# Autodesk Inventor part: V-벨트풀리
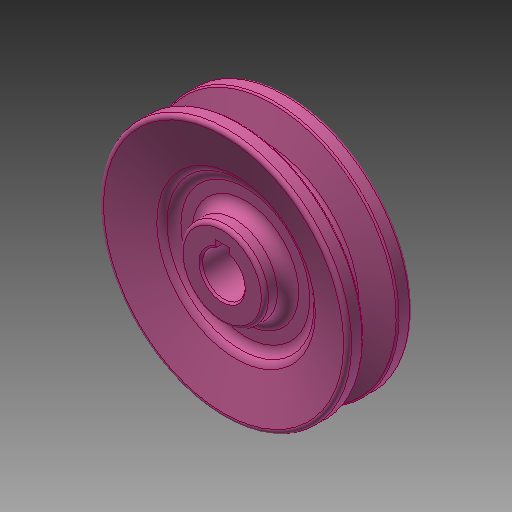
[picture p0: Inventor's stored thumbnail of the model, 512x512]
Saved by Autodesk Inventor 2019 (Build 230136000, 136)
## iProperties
Created: 2016-08
Part Number: V-벨트풀리
Material: 알루미늄 6061
Document SubType Name: Modeling
Designer: mduedu
Density: 2.71 g/cm^3
Appearance: 분홍색
Author: mduedu
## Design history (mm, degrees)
sketch "스케치1"
  geometry: L1 (0, 9.5)-(0, -9.5); L2 (0, 9.5)-(35, 9.5); L3 (35, 9.5)-(35, 4.825); L4 (35, 4.825)-(26, 2.074); L5 (26, 2.074)-(26, 0); L6 (0, 0)-(26, 0); L7 (0, -9.5)-(35, -9.5); L8 (35, -9.5)-(35, -4.825); L9 (35, -4.825)-(26, -2.074); L10 (26, -2.074)-(26, 0); L11 (32.3, 9.5)-(32.3, -9.5); 3 further points
  constraints: 22 end point, 6 point on line, 4 perpendicular, 3 symmetric about line, 1 coincident, 1 horizontal alignment, 1 midpoint, 1 parallel, 1 vertical
  dimensions: "d0" = 19 distance of L1.start L1.end; "d2" = 70 diameter of L8 L1; "d4" = 6.3 distance between parallel lines of L10 L11; "d5" = 2.7 distance between parallel lines of L11 L8; "d6" = 8 distance of point (32.3, -4) point (32.3, 4); "d7" = 34 deg angle of L9 L4
revolve "회전1" sketch "스케치1" stored, may be unused: angle "d8" = 90 deg
sketch "스케치2"
  geometry: L1 (-2, 0)-(2, 0); L2 (2, 0)-(2, 7.8); L3 (2, 7.8)-(-2, 7.8); L4 (-2, 7.8)-(-2, 0); C1 r 6 at (0, 0); 2 further points
  constraints: 8 end point, 2 coincident, 2 parallel, 1 centre point, 1 horizontal, 1 midpoint, 1 perpendicular
  dimensions: "d9" = 12 diameter of C1; "d11" = 4 distance of L2.end L3.end; "d12" = 7.8 distance of L1.end L2.end
extrude "돌출1" cut sketch "스케치2" extent not by distance; stored distance "d13" = 10; taper "d14" = 0 deg
sketch "스케치3"
  geometry: L1 (35, 4.825)-(26, 2.074) reference; L2 (26, 2.074)-(26, -2.074) reference; L3 (0, 0)-(26, 0); L4 (35, 9.5)-(35, 4.825) reference; L5 (-35, 9.5)-(35, 9.5) reference; L6 (35, 9.5)-(21, 5.22); L7 (21, 5.22)-(21, 3); L8 (21, 3)-(12, 3); L9 (12, 3)-(12, 9.5); L10 (0, 9.5)-(0, -9.5); L11 (5.657, -9.5)-(-6, -9.5) reference; L12 (12, 9.5)-(35, 9.5)
  constraints: 14 end point, 3 midpoint, 2 parallel, 2 perpendicular, 2 point on line, 1 collinear, 1 horizontal
  dimensions: "d15" = 3 distance between parallel lines of L3 L8; "d17" = 42 diameter of L7 L10; "d18" = 24 diameter of L9 L10
revolve "회전2" sketch "스케치3" stored, may be unused: angle "d19" = 90 deg
fillet "모깎기1" dims "d20" = 0.5, "d21" = 1, "d22" = 1
fillet "모깎기2" dims "d23" = 3
fillet "모깎기3" dims "d24" = 3
fillet "모깎기4" dims "d25" = 3
chamfer "모따기1" distance "d26" = 0.5; stored, may be unused: second distance "d27" = 2, angle "d28" = 45 deg
fillet "모깎기5" dims "d29" = 1
node "솔리드1"
mirror "대칭1"
